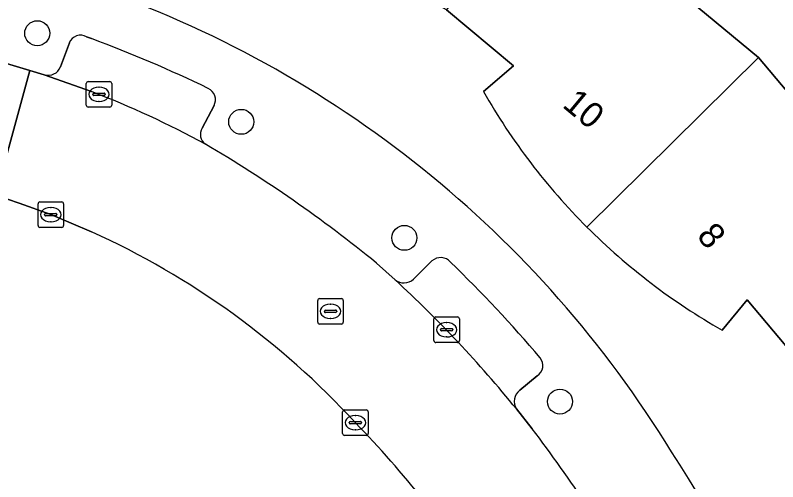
# Model space of a CAD drawing. Extents: x 159053 to 160042, y 380449 to 381423.
# Drawn here: x 159497.02 to 159526.86, y 380864.74 to 380883.02 of the extents above; entities that cross this region are included whole.
import ezdxf

# ---------------------------------------------------------------- set-up
doc = ezdxf.new("R2010")
doc.units = 0
for name, color, linetype in [('IMGEO_Boom', 7, 'Continuous'), ('IMGEO_Erf', 7, 'Continuous'), ('IMGEO_Groenvoorziening', 7, 'Continuous'), ('IMGEO_Kolk', 7, 'Continuous'), ('IMGEO_Pand', 7, 'Continuous'), ('IMGEO_Pand_nummerreeks', 7, 'Continuous'), ('IMGEO_Parkeervlak_open', 7, 'Continuous'), ('IMGEO_Rijbaan_lokaal_open', 7, 'Continuous'), ('IMGEO_Rioolput', 7, 'Continuous'), ('IMGEO_Voetpad_open', 7, 'Continuous')]:
    doc.layers.add(name, color=color, linetype=linetype)

msp = doc.modelspace()

# ---------------------------------------------------------------- linework, layer by layer
at = {"layer": 'IMGEO_Boom'}
for centre in [(159497.875, 380882.316), (159505.861, 380878.844), (159512.248, 380874.299), (159518.338, 380867.883)]:
    msp.add_circle(centre, 0.489, dxfattribs=at)
at = {"layer": 'IMGEO_Erf'}
for points in [[(159500, 380887.872), (159498.336, 380889.178), (159499.11, 380890.546), (159498.705, 380890.693), (159495.677, 380891.788), (159497.327, 380897.94), (159498.048, 380900.63), (159502.961, 380898.82), (159509.178, 380896.53), (159508, 380893.993), (159517.592, 380888.432), (159526.109, 380881.368), (159533.241, 380872.87)], [(159515.347, 380880.028), (159516.522, 380881.044), (159513.892, 380883.235), (159510.816, 380884.987), (159510.323, 380883.572)], [(159528.217, 380865.632), (159529.662, 380866.173), (159527.931, 380869.165), (159525.661, 380871.869), (159524.686, 380870.684)]]:
    msp.add_lwpolyline(points, dxfattribs=at)
for centre, radius, start, end in [((159486.084, 380843.565), 42.9, 31.404, 71.071), ((159537.029, 380892.355), 24.941, 209.621, 225.0044), ((159537.046, 380892.386), 24.975, 225.0268, 240.338), ((159479.625, 380837.852), 51.411, 10.905, 33.0883)]:
    msp.add_arc(centre, radius, start, end, dxfattribs=at)
at = {"layer": 'IMGEO_Groenvoorziening'}
msp.add_lwpolyline([(159500, 380874.538), (159498.404, 380875.21), (159497.175, 380875.659), (159496.247, 380875.965)], dxfattribs=at)
for centre, radius, start, end in [((159486.779, 380845.41), 31.988, 42.5905, 65.5873), ((159480.923, 380838.553), 40.954, 38.3899, 44.1086)]:
    msp.add_arc(centre, radius, start, end, dxfattribs=at)
at = {"layer": 'IMGEO_Kolk'}
for p, q in [((159499.794, 380879.496), (159499.794, 380880.348)), ((159499.869, 380880.422), (159500.721, 380880.422)), ((159500.282, 380880.202), (159500.307, 380880.202)), ((159500.795, 380880.348), (159500.795, 380879.496)), ((159500.053, 380879.916), (159500.053, 380879.928)), ((159500.096, 380879.965), (159500.494, 380879.965)), ((159500.537, 380879.928), (159500.537, 380879.916)), ((159500.491, 380879.879), (159500.093, 380879.879)), ((159500.305, 380879.642), (159500.28, 380879.642)), ((159500.721, 380879.422), (159499.869, 380879.422)), ((159497.907, 380874.783), (159497.907, 380875.635)), ((159497.982, 380875.709), (159498.834, 380875.709)), ((159498.395, 380875.489), (159498.42, 380875.489)), ((159498.908, 380875.635), (159498.908, 380874.783)), ((159498.166, 380875.203), (159498.166, 380875.215)), ((159498.604, 380875.166), (159498.206, 380875.166)), ((159498.209, 380875.252), (159498.607, 380875.252)), ((159498.65, 380875.215), (159498.65, 380875.203)), ((159498.418, 380874.929), (159498.393, 380874.929)), ((159498.834, 380874.709), (159497.982, 380874.709)), ((159513.401, 380870.272), (159513.401, 380871.124)), ((159513.476, 380871.198), (159514.328, 380871.198)), ((159513.889, 380870.978), (159513.914, 380870.978)), ((159514.402, 380871.124), (159514.402, 380870.272)), ((159513.66, 380870.692), (159513.66, 380870.704)), ((159514.098, 380870.655), (159513.7, 380870.655)), ((159513.703, 380870.741), (159514.101, 380870.741)), ((159514.144, 380870.704), (159514.144, 380870.692)), ((159513.912, 380870.418), (159513.887, 380870.418)), ((159514.328, 380870.198), (159513.476, 380870.198)), ((159509.831, 380866.631), (159509.831, 380867.483)), ((159509.906, 380867.557), (159510.758, 380867.557)), ((159510.832, 380867.483), (159510.832, 380866.631)), ((159510.09, 380867.051), (159510.09, 380867.063)), ((159510.133, 380867.1), (159510.531, 380867.1)), ((159510.319, 380867.337), (159510.344, 380867.337)), ((159510.574, 380867.063), (159510.574, 380867.051)), ((159510.528, 380867.014), (159510.13, 380867.014)), ((159510.342, 380866.777), (159510.317, 380866.777)), ((159510.758, 380866.557), (159509.906, 380866.557))]:
    msp.add_line(p, q, dxfattribs=at)
for points in [[(159499.794, 380879.496), (159499.794, 380880.348)], [(159499.869, 380880.422), (159500.721, 380880.422)], [(159500.795, 380880.348), (159500.795, 380879.496)], [(159500.721, 380879.422), (159499.869, 380879.422)], [(159497.907, 380874.783), (159497.907, 380875.635)], [(159497.982, 380875.709), (159498.834, 380875.709)], [(159498.908, 380875.635), (159498.908, 380874.783)], [(159498.834, 380874.709), (159497.982, 380874.709)], [(159513.401, 380870.272), (159513.401, 380871.124)], [(159513.476, 380871.198), (159514.328, 380871.198)], [(159514.402, 380871.124), (159514.402, 380870.272)], [(159514.328, 380870.198), (159513.476, 380870.198)], [(159509.831, 380866.631), (159509.831, 380867.483)], [(159509.906, 380867.557), (159510.758, 380867.557)], [(159510.832, 380867.483), (159510.832, 380866.631)], [(159510.758, 380866.557), (159509.906, 380866.557)]]:
    msp.add_lwpolyline(points, dxfattribs=at)
for centre, radius, start, end in [((159499.871, 380880.346), 0.0765, 91.552, 178.448), ((159499.871, 380880.346), 0.0765, 91.552, 178.448), ((159500.719, 380880.346), 0.0765, 1.552, 88.448), ((159500.719, 380880.346), 0.0765, 1.552, 88.448), ((159500.093, 380879.925), 0.0403, 85.8775, 175.7526), ((159500.09, 380879.915), 0.0366, 178.938, 274.7102), ((159500.494, 380879.922), 0.043, 264.8664, 352.4533), ((159500.498, 380879.927), 0.0386, 1.7309, 96.639), ((159499.871, 380879.498), 0.0765, 181.552, 268.448), ((159499.871, 380879.498), 0.0765, 181.552, 268.448), ((159500.719, 380879.498), 0.0765, 271.552, 358.448), ((159500.719, 380879.498), 0.0765, 271.552, 358.448), ((159497.984, 380875.633), 0.0765, 91.552, 178.448), ((159497.984, 380875.633), 0.0765, 91.552, 178.448), ((159498.832, 380875.633), 0.0765, 1.552, 88.448), ((159498.832, 380875.633), 0.0765, 1.552, 88.448), ((159498.206, 380875.212), 0.0403, 85.8775, 175.7526), ((159498.203, 380875.202), 0.0366, 178.938, 274.7102), ((159498.607, 380875.209), 0.043, 264.8664, 352.4533), ((159498.611, 380875.214), 0.0386, 1.7309, 96.639), ((159497.984, 380874.785), 0.0765, 181.552, 268.448), ((159497.984, 380874.785), 0.0765, 181.552, 268.448), ((159498.832, 380874.785), 0.0765, 271.552, 358.448), ((159498.832, 380874.785), 0.0765, 271.552, 358.448), ((159513.478, 380871.122), 0.0765, 91.552, 178.448), ((159513.478, 380871.122), 0.0765, 91.552, 178.448), ((159514.326, 380871.122), 0.0765, 1.552, 88.448), ((159514.326, 380871.122), 0.0765, 1.552, 88.448), ((159513.7, 380870.701), 0.0403, 85.8775, 175.7526), ((159513.697, 380870.691), 0.0366, 178.938, 274.7102), ((159514.101, 380870.698), 0.043, 264.8664, 352.4533), ((159514.105, 380870.703), 0.0386, 1.7309, 96.639), ((159513.478, 380870.274), 0.0765, 181.552, 268.448), ((159513.478, 380870.274), 0.0765, 181.552, 268.448), ((159514.326, 380870.274), 0.0765, 271.552, 358.448), ((159514.326, 380870.274), 0.0765, 271.552, 358.448), ((159509.908, 380867.481), 0.0765, 91.552, 178.448), ((159509.908, 380867.481), 0.0765, 91.552, 178.448), ((159510.756, 380867.481), 0.0765, 1.552, 88.448), ((159510.756, 380867.481), 0.0765, 1.552, 88.448), ((159510.13, 380867.06), 0.0403, 85.8775, 175.7526), ((159510.535, 380867.062), 0.0386, 1.7309, 96.639), ((159510.127, 380867.05), 0.0366, 178.938, 274.7102), ((159510.531, 380867.057), 0.043, 264.8664, 352.4533), ((159509.908, 380866.633), 0.0765, 181.552, 268.448), ((159509.908, 380866.633), 0.0765, 181.552, 268.448), ((159510.756, 380866.633), 0.0765, 271.552, 358.448), ((159510.756, 380866.633), 0.0765, 271.552, 358.448)]:
    msp.add_arc(centre, radius, start, end, dxfattribs=at)
for centre, major_axis, ratio, start_param, end_param in [((159500.281, 380879.922), (-0.387, 0.002), 0.722429, 4.712389, 7.853982), ((159500.306, 380879.922), (-0.39, 0.002), 0.717154, 1.570796, 4.712389), ((159498.394, 380875.209), (-0.387, 0.002), 0.722429, 4.712389, 7.853982), ((159498.419, 380875.209), (-0.39, 0.002), 0.717154, 1.570796, 4.712389), ((159513.888, 380870.698), (-0.387, 0.002), 0.722429, 4.712389, 7.853982), ((159513.913, 380870.698), (-0.39, 0.002), 0.717154, 1.570796, 4.712389), ((159510.318, 380867.057), (-0.387, 0.002), 0.722429, 4.712389, 7.853982), ((159510.343, 380867.057), (-0.39, 0.002), 0.717154, 1.570796, 4.712389)]:
    msp.add_ellipse(centre, major_axis=major_axis, ratio=ratio, start_param=start_param, end_param=end_param, dxfattribs=at)
at = {"layer": 'IMGEO_Pand'}
for points in [[(159519.394, 380874.718), (159526.109, 380881.368), (159517.592, 380888.432), (159513.892, 380883.235), (159516.522, 380881.044), (159515.347, 380880.028)], [(159524.686, 380870.684), (159525.661, 380871.869), (159527.931, 380869.165), (159533.241, 380872.87), (159526.109, 380881.368), (159519.394, 380874.718)]]:
    msp.add_lwpolyline(points, dxfattribs=at)
for centre, radius, start, end in [((159537.029, 380892.355), 24.941, 209.621, 225.0044), ((159537.046, 380892.386), 24.975, 225.0268, 240.338)]:
    msp.add_arc(centre, radius, start, end, dxfattribs=at)
at = {"layer": 'IMGEO_Parkeervlak_open'}
for points in [[(159500, 380882.106), (159499.808, 380882.178)], [(159499.133, 380881.938), (159498.783, 380881.002)], [(159498.154, 380880.684), (159500, 380880.029)], [(159504.334, 380878.594), (159504.797, 380879.481)], [(159513.327, 380873.396), (159512.602, 380872.676)], [(159516.769, 380868.33), (159517.45, 380868.893)]]:
    msp.add_lwpolyline(points, dxfattribs=at)
for centre, radius, start, end in [((159499.578, 380881.756), 0.481, 61.3818, 157.7645), ((159480.384, 380829.843), 55.823, 64.324, 69.4272), ((159498.297, 380881.183), 0.519, 254.0587, 339.5803), ((159486.561, 380845.059), 37.463, 61.4626, 68.9774), ((159504.356, 380879.707), 0.496, 332.8201, 64.305), ((159504.722, 380878.347), 0.46, 147.5502, 234.9635), ((159513.665, 380873.014), 0.511, 40.9225, 131.4914), ((159479.039, 380837.088), 50.404, 40.1625, 46.0029), ((159512.23, 380873.084), 0.552, 230.8098, 312.3681), ((159479.235, 380837.249), 48.16, 39.0576, 47.3232), ((159517.184, 380869.295), 0.482, 303.534, 38.8637), ((159517.099, 380867.888), 0.552, 126.7947, 212.0884)]:
    msp.add_arc(centre, radius, start, end, dxfattribs=at)
at = {"layer": 'IMGEO_Rijbaan_lokaal_open'}
for points in [[(159496.247, 380875.965), (159497.584, 380880.855), (159496.273, 380881.248), (159494.349, 380881.806)], [(159500, 380880.029), (159498.154, 380880.684), (159497.584, 380880.855), (159496.247, 380875.965), (159497.175, 380875.659), (159498.404, 380875.21), (159500, 380874.538)], [(159511.881, 380872.656), (159511.153, 380873.313)], [(159517.247, 380866.821), (159516.632, 380867.595)]]:
    msp.add_lwpolyline(points, dxfattribs=at)
for centre, radius, start, end in [((159486.561, 380845.059), 37.463, 61.4626, 68.9774), ((159477.445, 380832.005), 53.316, 50.7853, 59.5587), ((159486.779, 380845.41), 31.988, 42.5905, 65.5873), ((159479.235, 380837.249), 48.16, 39.0576, 47.3232), ((159480.923, 380838.553), 40.954, 38.3899, 44.1086), ((159477.57, 380836.473), 49.953, 28.7692, 37.4119)]:
    msp.add_arc(centre, radius, start, end, dxfattribs=at)
at = {"layer": 'IMGEO_Rioolput'}
for p, q in [((159508.856, 380870.996), (159508.856, 380871.848)), ((159508.931, 380871.922), (159509.783, 380871.922)), ((159509.857, 380871.848), (159509.857, 380870.996)), ((159509.344, 380871.702), (159509.369, 380871.702)), ((159509.115, 380871.416), (159509.115, 380871.428)), ((159509.553, 380871.379), (159509.155, 380871.379)), ((159509.158, 380871.465), (159509.556, 380871.465)), ((159509.599, 380871.428), (159509.599, 380871.416)), ((159509.367, 380871.142), (159509.342, 380871.142)), ((159509.783, 380870.922), (159508.931, 380870.922))]:
    msp.add_line(p, q, dxfattribs=at)
for points in [[(159508.856, 380870.996), (159508.856, 380871.848)], [(159508.931, 380871.922), (159509.783, 380871.922)], [(159509.857, 380871.848), (159509.857, 380870.996)], [(159509.783, 380870.922), (159508.931, 380870.922)]]:
    msp.add_lwpolyline(points, dxfattribs=at)
for centre, radius, start, end in [((159508.933, 380871.846), 0.0765, 91.552, 178.448), ((159508.933, 380871.846), 0.0765, 91.552, 178.448), ((159509.781, 380871.846), 0.0765, 1.552, 88.448), ((159509.781, 380871.846), 0.0765, 1.552, 88.448), ((159509.155, 380871.425), 0.0403, 85.8775, 175.7526), ((159509.152, 380871.415), 0.0366, 178.938, 274.7102), ((159509.556, 380871.422), 0.043, 264.8664, 352.4533), ((159509.56, 380871.427), 0.0386, 1.7309, 96.639), ((159508.933, 380870.998), 0.0765, 181.552, 268.448), ((159508.933, 380870.998), 0.0765, 181.552, 268.448), ((159509.781, 380870.998), 0.0765, 271.552, 358.448), ((159509.781, 380870.998), 0.0765, 271.552, 358.448)]:
    msp.add_arc(centre, radius, start, end, dxfattribs=at)
for centre, major_axis, ratio, start_param, end_param in [((159509.343, 380871.422), (-0.387, 0.002), 0.722429, 4.712389, 7.853982), ((159509.368, 380871.422), (-0.39, 0.002), 0.717154, 1.570796, 4.712389)]:
    msp.add_ellipse(centre, major_axis=major_axis, ratio=ratio, start_param=start_param, end_param=end_param, dxfattribs=at)
at = {"layer": 'IMGEO_Voetpad_open'}
for points in [[(159499.808, 380882.178), (159500, 380882.106)], [(159494.349, 380881.806), (159496.273, 380881.248), (159497.584, 380880.855), (159498.154, 380880.684)], [(159498.783, 380881.002), (159499.133, 380881.938)], [(159504.797, 380879.481), (159504.334, 380878.594)], [(159512.602, 380872.676), (159513.327, 380873.396)], [(159511.153, 380873.313), (159511.881, 380872.656)], [(159517.45, 380868.893), (159516.769, 380868.33)], [(159516.632, 380867.595), (159517.247, 380866.821)]]:
    msp.add_lwpolyline(points, dxfattribs=at)
for centre, radius, start, end in [((159486.084, 380843.565), 42.9, 31.404, 71.071), ((159499.578, 380881.756), 0.481, 61.3818, 157.7645), ((159480.384, 380829.843), 55.823, 64.324, 69.4272), ((159498.297, 380881.183), 0.519, 254.0587, 339.5803), ((159504.356, 380879.707), 0.496, 332.8201, 64.305), ((159504.722, 380878.347), 0.46, 147.5502, 234.9635), ((159477.445, 380832.005), 53.316, 50.7853, 59.5587), ((159513.665, 380873.014), 0.511, 40.9225, 131.4914), ((159479.039, 380837.088), 50.404, 40.1625, 46.0029), ((159512.23, 380873.084), 0.552, 230.8098, 312.3681), ((159517.184, 380869.295), 0.482, 303.534, 38.8637), ((159517.099, 380867.888), 0.552, 126.7947, 212.0884), ((159477.57, 380836.473), 49.953, 28.7692, 37.4119), ((159479.625, 380837.852), 51.411, 10.905, 33.0883)]:
    msp.add_arc(centre, radius, start, end, dxfattribs=at)

# ---------------------------------------------------------------- texts
at = {"layer": 'IMGEO_Pand_nummerreeks'}
for s, rotation, p in [('10', 320.2008, (159518.389, 380879.453)), ('8', 310.0733, (159523.657, 380874.355))]:
    msp.add_text(s, height=1, rotation=rotation, dxfattribs=at).set_placement(p)

doc.saveas('drawing.dxf')
